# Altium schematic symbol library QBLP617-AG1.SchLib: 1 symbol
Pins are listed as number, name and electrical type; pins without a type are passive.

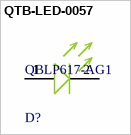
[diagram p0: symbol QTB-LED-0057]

## QTB-LED-0057
designator D?, comment QBLP617-AG1
LED YELLOW/GREEN CLEAR 0602 SMD, RIGHT ANGLE; Manufacturer: QT Brightek (QTB); Test Current: 20mA; Lens Size: 0.6mm; Dominant Wavelength: 570nm; Luminous Intensity: 45mcd; Forward Voltage: 2.0V; Viewing Angle: 140°; Lens Style: Rectangle with Flat Top; Lens Color: Colorless
footprint QBLP617-AG-MFG
pins: 1 ANODE (+), 2 CATHODE (-)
